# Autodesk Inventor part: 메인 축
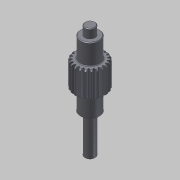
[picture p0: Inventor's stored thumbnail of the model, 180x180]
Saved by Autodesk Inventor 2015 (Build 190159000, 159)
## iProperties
Created: 2016-02
Part Number: 메인 축
Material: 강철, 연강
Document SubType Name: Modeling
Categories: <?xml version="1.0" encoding="UTF-16"?> <MemberInstance><Categories><FamilyTemplate><FamilyTemplateParameter ValueType="xs:double" Id="1" ObjectReferenceKey="da
Density: 7.86 g/cm^3
Appearance: Steel
CustomPartVersion: 1
Author: mdu
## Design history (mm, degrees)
sketch "Sketch1"
  geometry: C1 r 12 at (0, 0)
  constraints: 1 centre point
  dimensions: "d0" = 24 diameter of C1 (= da_da)
extrude "Extrusion1" new body sketch "Sketch1" distance "d1" = 20 (= da_b); taper "d2" = 0 deg
workplane "Work Plane2"
feature "피치 지름" dims "d4" = 10, "d5" = 0
workplane "Work Plane8"
workplane "Work Plane9"
chamfer "모따기1" distance "d49" = 1; stored, may be unused: second distance "d50" = 2, angle "d51" = 45 deg
sketch "스케치3"
  geometry: C1 r 7.5 at (0, 0); 1 further point
  constraints: 1 centre point, 1 coincident
  dimensions: "d52" = 15 diameter of C1
extrude "돌출2" join sketch "스케치3" distance "d53" = 16; taper "d54" = 0 deg
sketch "스케치4"
  geometry: C1 r 4 at (0, 0); 1 further point
  constraints: 1 centre point, 1 coincident
  dimensions: "d55" = 8 diameter of C1
extrude "돌출3" join sketch "스케치4" distance "d56" = 7; taper "d57" = 0 deg
sketch "스케치5"
  geometry: C1 r 7.5 at (0, 0) reference; C2 r 7.5 at (0, 0) reference; 1 further point
extrude "돌출4" join sketch "스케치5" distance "d62" = 16; taper "d63" = 0 deg
sketch "스케치6"
  geometry: C1 r 4 at (0, 0); 1 further point
  constraints: 1 centre point, 1 coincident
  dimensions: "d64" = 8 diameter of C1
extrude "돌출5" join sketch "스케치6" distance "d65" = 30; taper "d66" = 0 deg
chamfer "모따기2" distance "d58" = 0.5; stored, may be unused: second distance "d59" = 2, angle "d60" = 45 deg
fillet "모깎기1" dims "d61" = 0.5
feature "스퍼 기어" dims "da_b" = 20, "da_d" = 22, "da_aw" = 31, "da_da" = 24, "da_df" = 19.5, "da_dw" = 22, angle "da_beta" = 0 deg, "da_lefttooth" = 0, "da_righttooth" = 0
body "Solid1"
sketch "Sketch2"
  geometry: C1 r 12 at (0, 0) reference; C2 r 11 at (0, 0)
  constraints: 1 centre point, 1 coincident
  dimensions: "d3" = 22 diameter of C2 (= da_dw)
body "Srf1"
node "투영된 루프1"
other parameters: "d16" = 31 (= da_aw), "d17" = 0, "d34" = 1.428 (computed from da_z), "d39" = 0, "d41" = 0, "d43" = 31 (= da_aw), "d46" = 31 (= da_aw), "d47" = 0, "d48" = 0
